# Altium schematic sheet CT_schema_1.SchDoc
size 547 x 505 mm
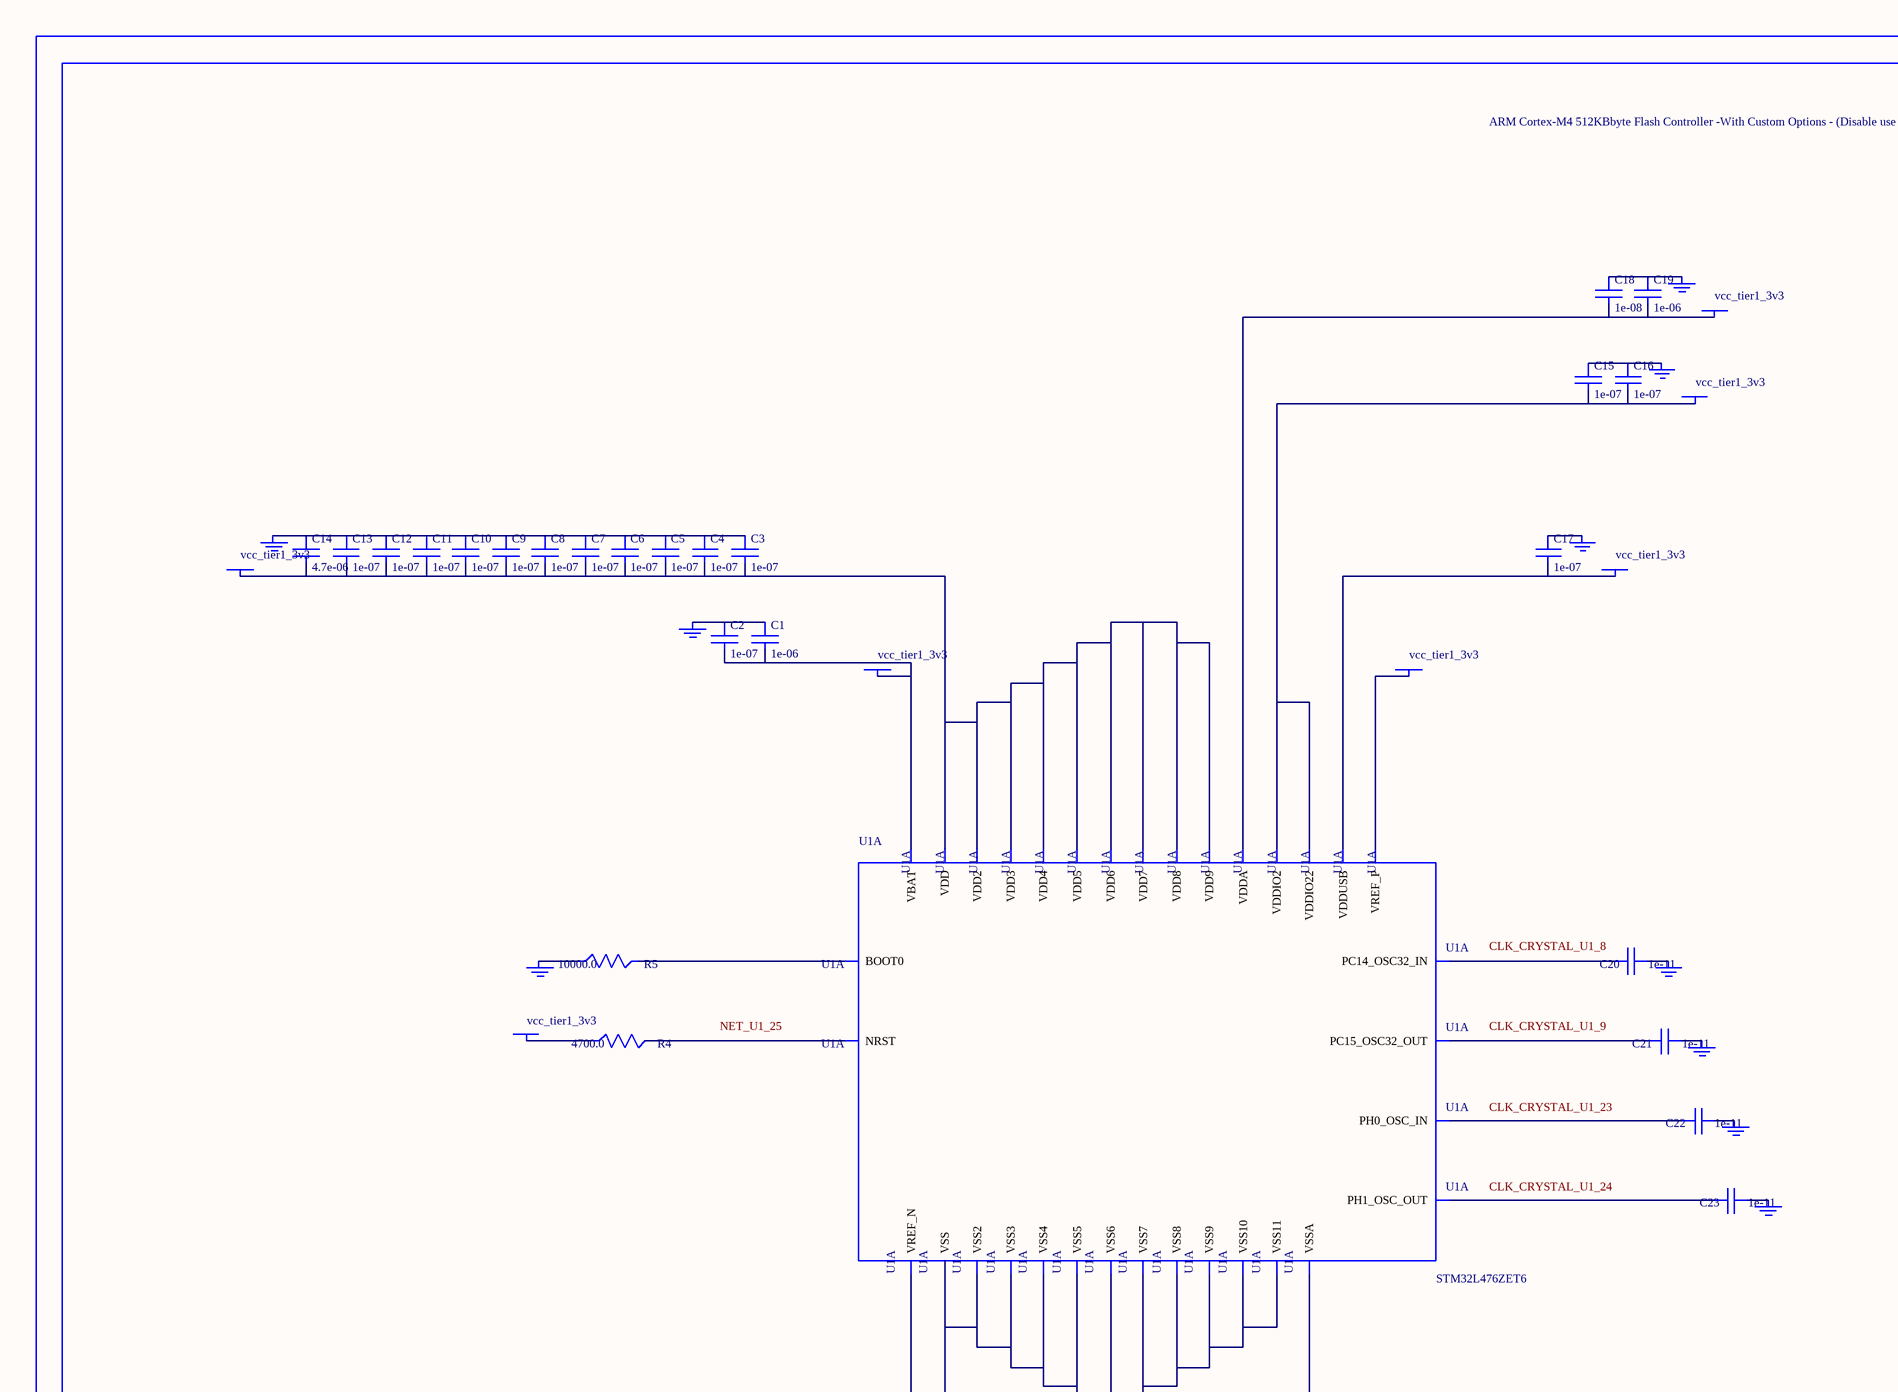
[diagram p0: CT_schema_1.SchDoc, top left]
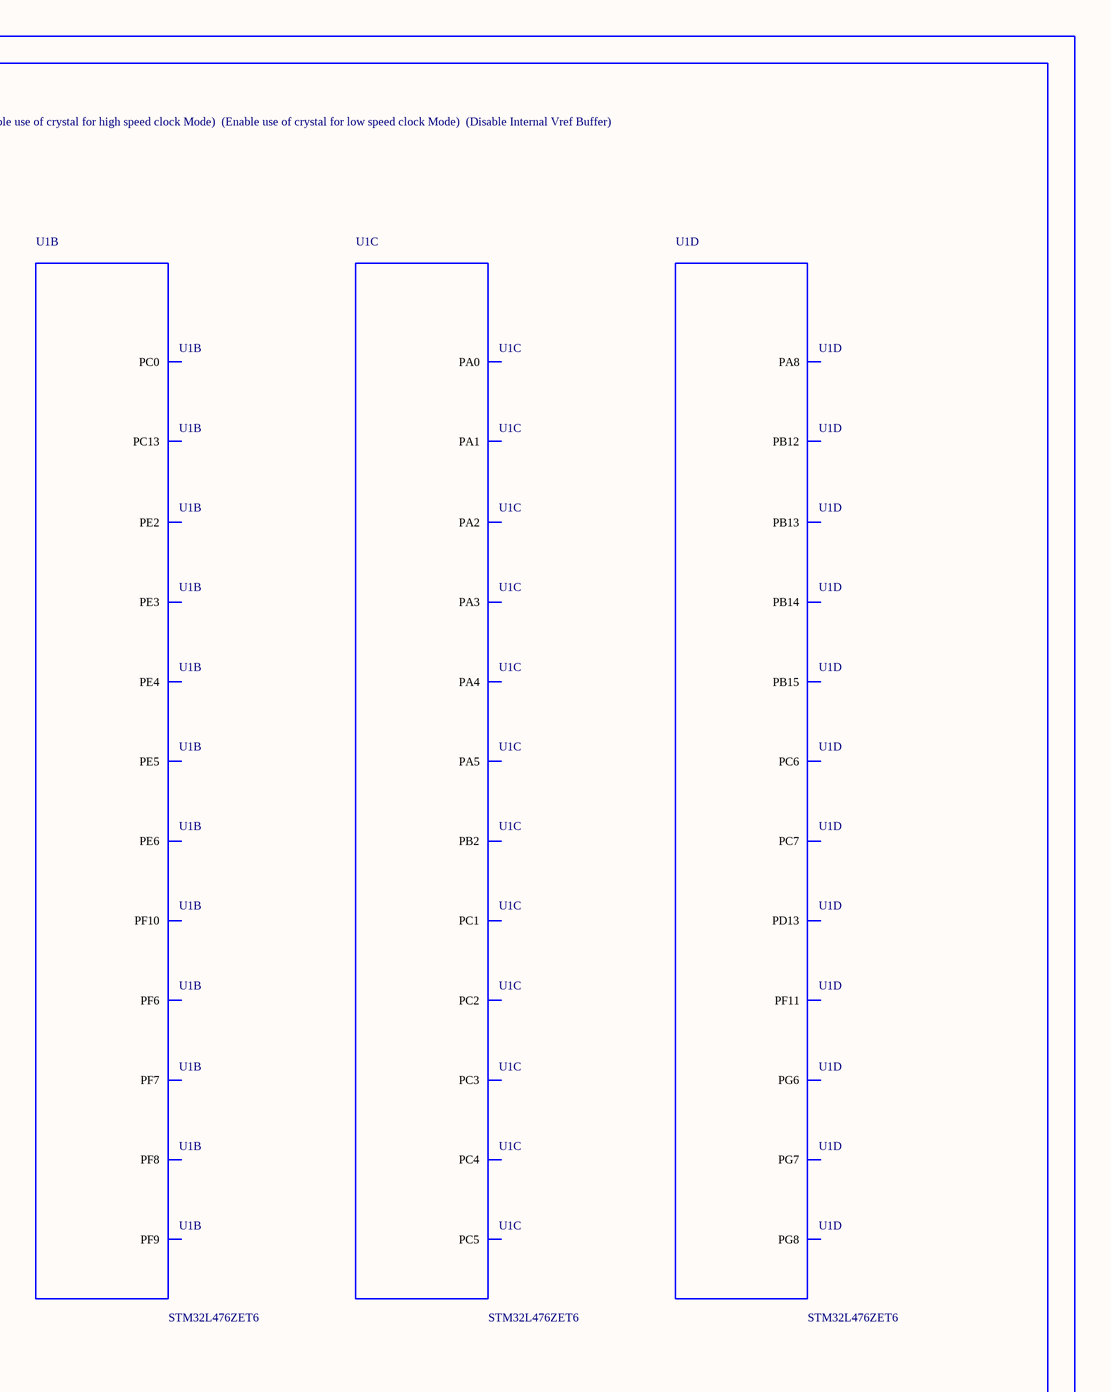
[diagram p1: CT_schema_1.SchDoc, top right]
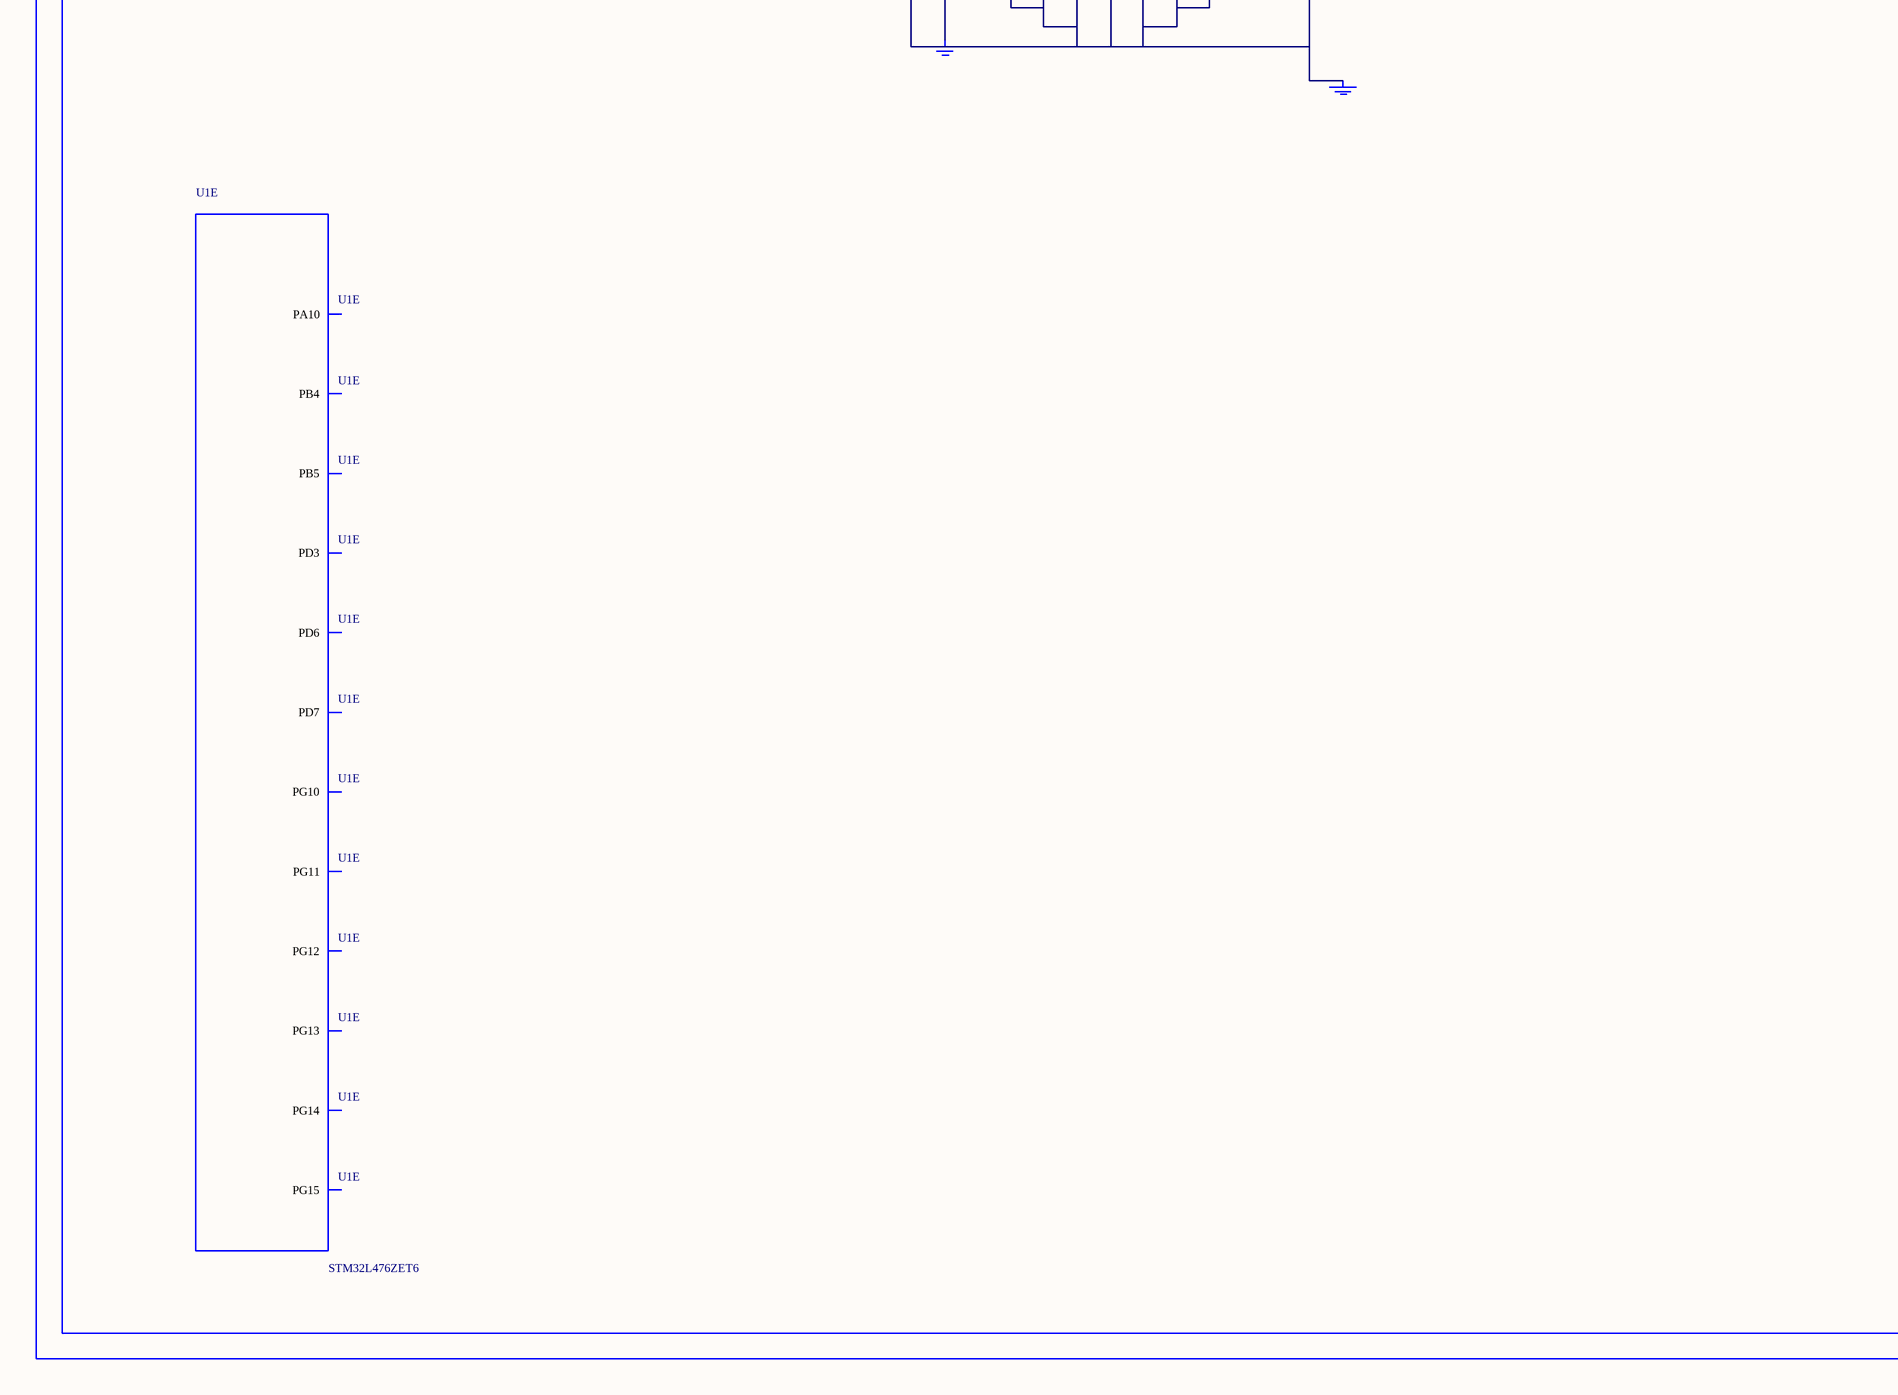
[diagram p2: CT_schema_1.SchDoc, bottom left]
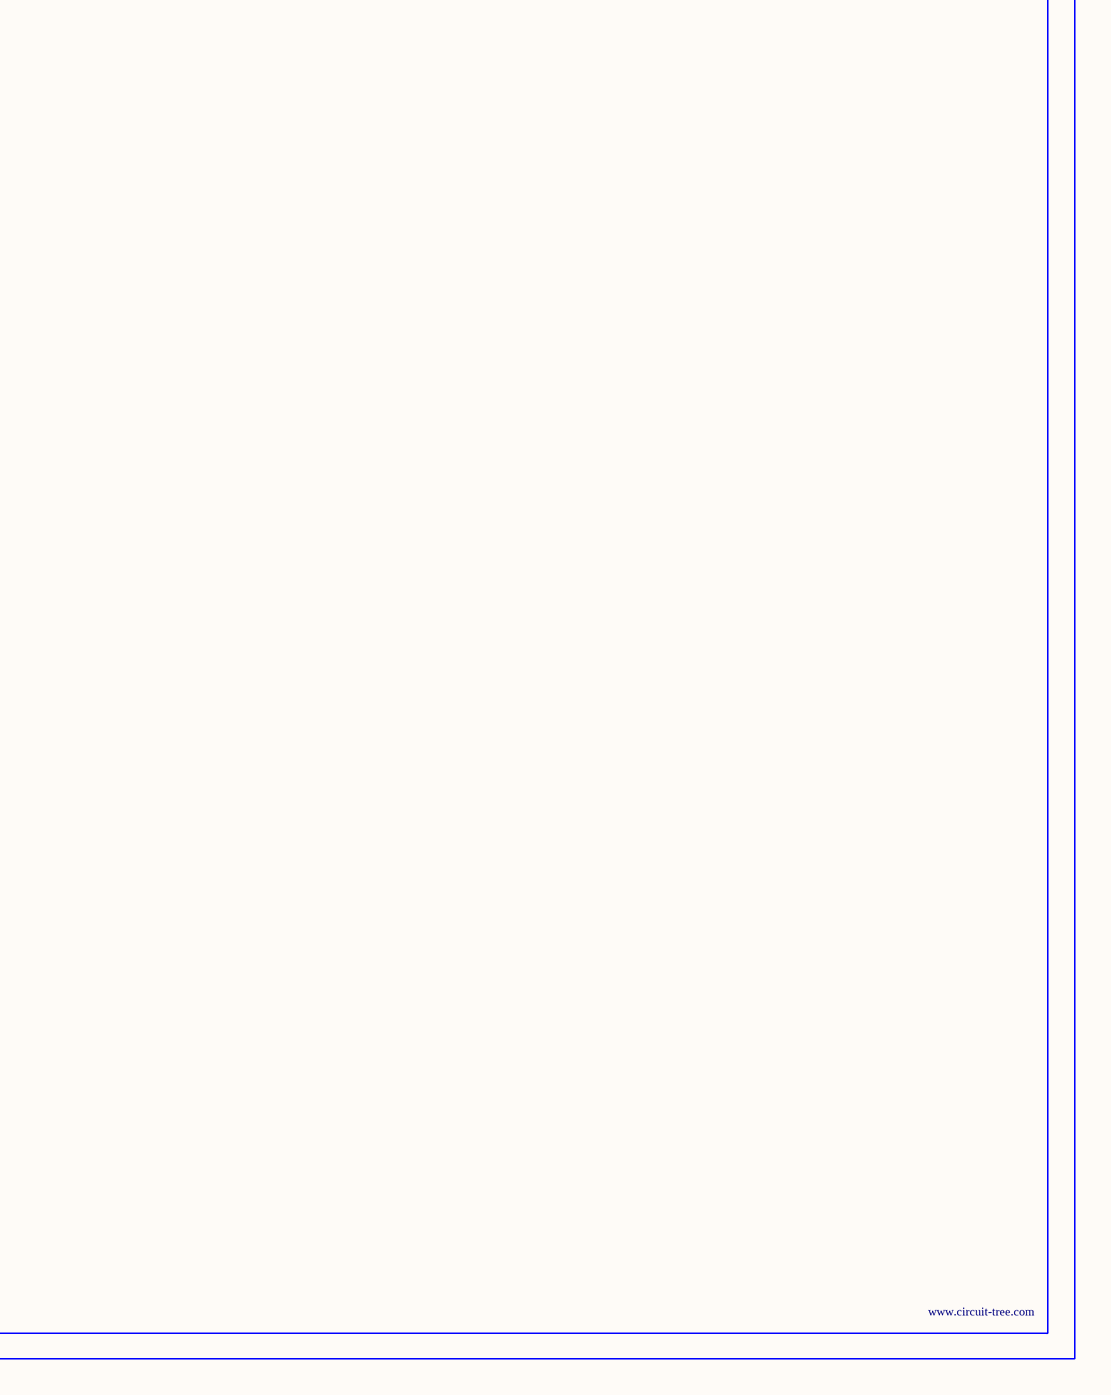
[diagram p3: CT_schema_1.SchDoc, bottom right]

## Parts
BORDER0  (no value)
C1  1e-06  [C0603]
C2  1e-07  [C0603]
C3  1e-07  [C0603]
C4  1e-07  [C0603]
C5  1e-07  [C0603]
C6  1e-07  [C0603]
C7  1e-07  [C0603]
C8  1e-07  [C0603]
C9  1e-07  [C0603]
C10  1e-07  [C0603]
C11  1e-07  [C0603]
C12  1e-07  [C0603]
C13  1e-07  [C0603]
C14  4.7e-06  [C0603]
C15  1e-07  [C0603]
C16  1e-07  [C0603]
C17  1e-07  [C0603]
C18  1e-08  [C0603]
C19  1e-06  [C0603]
C20  1e-11  [C0402]
C21  1e-11  [C0402]
C22  1e-11  [C0402]
C23  1e-11  [C0402]
GND_INSTANCE_0_0  (no value)
GND_INSTANCE_0_1  (no value)
GND_INSTANCE_0_2  (no value)
GND_INSTANCE_0_3  (no value)
GND_INSTANCE_0_4  (no value)
GND_INSTANCE_0_5  (no value)
GND_INSTANCE_0_6  (no value)
GND_INSTANCE_0_7  (no value)
GND_INSTANCE_0_8  (no value)
GND_INSTANCE_0_9  (no value)
GND_INSTANCE_0_10  (no value)
GND_INSTANCE_0_11  (no value)
POWER_INSTANCE_0_0  vcc_tier1_3v3
POWER_INSTANCE_0_1  vcc_tier1_3v3
POWER_INSTANCE_0_2  vcc_tier1_3v3
POWER_INSTANCE_0_3  vcc_tier1_3v3
POWER_INSTANCE_0_4  vcc_tier1_3v3
POWER_INSTANCE_0_5  vcc_tier1_3v3
POWER_INSTANCE_0_6  vcc_tier1_3v3
R4  4700.0  [R0603]
R5  10000.0  [R0603]
U1  STM32L476ZET6  [LQFP144]  (parts A,B,C,D,E of 13)

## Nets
NetC1_1: C1.1 C2.1 GND_INSTANCE_0_0.0(GND)
NetC1_2: C1.2 C2.2 POWER_INSTANCE_0_0.0(PWR) U1.6(VBAT)
NetC3_1: C3.1 C4.1 C5.1 C6.1 C7.1 C8.1 C9.1 C10.1 C11.1 C12.1 C13.1 C14.1 GND_INSTANCE_0_3.0(GND)
NetC3_2: C3.2 C4.2 C5.2 C6.2 C7.2 C8.2 C9.2 C10.2 C11.2 C12.2 C13.2 C14.2 POWER_INSTANCE_0_1.0(PWR) U1.17(VDD) U1.39(VDD2) U1.52(VDD3) U1.62(VDD4) U1.72(VDD5) U1.84(VDD6) U1.108(VDD7) U1.121(VDD8) U1.144(VDD9)
NetC15_1: C15.1 C16.1 GND_INSTANCE_0_8.0(GND)
NetC15_2: C15.2 C16.2 POWER_INSTANCE_0_4.0(PWR) U1.95(VDDIO2) U1.131(VDDIO22)
NetC17_1: C17.1 GND_INSTANCE_0_9.0(GND)
NetC17_2: C17.2 POWER_INSTANCE_0_5.0(PWR) U1.106(VDDUSB)
NetC18_1: C18.1 C19.1 GND_INSTANCE_0_7.0(GND)
NetC18_2: C18.2 C19.2 POWER_INSTANCE_0_3.0(PWR) U1.33(VDDA)
NetC20_1: C20.1 GND_INSTANCE_0_1.0(GND)
NetC20_2: C20.2 U1.8(PC14_OSC32_IN)
NetC21_1: C21.1 GND_INSTANCE_0_2.0(GND)
NetC21_2: C21.2 U1.9(PC15_OSC32_OUT)
NetC22_1: C22.1 GND_INSTANCE_0_4.0(GND)
NetC22_2: C22.2 U1.23(PH0_OSC_IN)
NetC23_1: C23.1 GND_INSTANCE_0_5.0(GND)
NetC23_2: C23.2 U1.24(PH1_OSC_OUT)
NetGND_INSTANCE_0_6_0: GND_INSTANCE_0_6.0(GND) GND_INSTANCE_0_11.0(GND) U1.16(VSS) U1.30(VSSA) U1.31(VREF_N) U1.38(VSS2) U1.51(VSS3) U1.61(VSS4) U1.71(VSS5) U1.83(VSS6) U1.94(VSS7) U1.107(VSS8) U1.120(VSS9) U1.130(VSS10) U1.143(VSS11)
NetGND_INSTANCE_0_10_0: GND_INSTANCE_0_10.0(GND) R5.1
NetPOWER_INSTANCE_0_2_0: POWER_INSTANCE_0_2.0(PWR) U1.32(VREF_P)
NetPOWER_INSTANCE_0_6_0: POWER_INSTANCE_0_6.0(PWR) R4.1
NetR4_2: R4.2 U1.25(NRST)
NetR5_2: R5.2 U1.138(BOOT0)

Not connected (* = marked no-connect by the designer): U1 1(PE2) 2(PE3) 3(PE4) 4(PE5) 5(PE6) 7(PC13) 18(PF6) 19(PF7) 20(PF8) 21(PF9) 22(PF10) 26(PC0) 27(PC1) 28(PC2) 29(PC3) 34(PA0) 35(PA1) 36(PA2) 37(PA3) 40(PA4) 41(PA5) 44(PC4) 45(PC5) 48(PB2) 49(PF11) 73(PB12) 74(PB13) 75(PB14) 76(PB15) 82(PD13) 91(PG6) 92(PG7) 93(PG8) 96(PC6) 97(PC7) 100(PA8) 102(PA10) 117(PD3) 122(PD6) 123(PD7) 125(PG10) 126(PG11) 127(PG12) 128(PG13) 129(PG14) 132(PG15) 134(PB4) 135(PB5)

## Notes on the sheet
- Labels drawn without touching a wire or pin: CLK_CRYSTAL_U1_8, CLK_CRYSTAL_U1_9, CLK_CRYSTAL_U1_23, CLK_CRYSTAL_U1_24, NET_U1_25

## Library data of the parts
BORDER0 = BORDER_PAGE0
C1 C19 = C0603C105K3RACTU
C2-C13 C15-C17 = 06035C104K4Z2A
C14 = GRM188R6YA475KE15D
C18 = 06035C103K4Z2A
C20-C23 = C0402C100K3GACTU
GND_INSTANCE_0_0-GND_INSTANCE_0_11 = GND
POWER_INSTANCE_0_0-POWER_INSTANCE_0_6 = PWR
R4 = RC0603JR-074K7L
R5 = RC0603JR-0710KL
